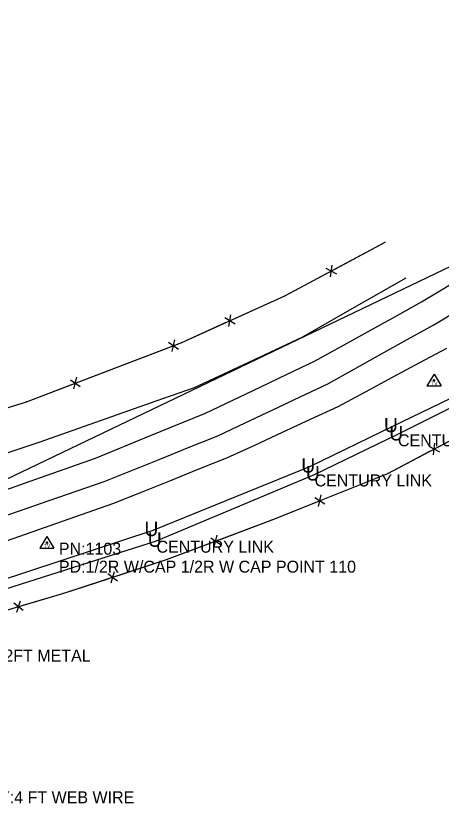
# Model space of a CAD drawing. Extents: x 1568433 to 1572450, y 731863 to 733450.
# Drawn here: x 1571582.8 to 1571760.5, y 732326.6 to 732655.4 of the extents above; entities that cross this region are included whole.
import ezdxf

# ---------------------------------------------------------------- set-up
doc = ezdxf.new("R2010")
doc.units = 0
for name, color, linetype in [('Default', 7, 'Continuous'), ('S_BASELINE', 7, 'Continuous'), ('S_DITCHLINE', 7, 'Continuous'), ('S_EDGE_PAVEMENT', 7, 'Continuous'), ('S_FENCE', 7, 'Continuous'), ('S_FENCE_ANNOT', 7, 'Continuous'), ('S_GATE_ANNOT', 7, 'Continuous'), ('S_MSC_PT_SYM', 7, 'Continuous'), ('S_PAVEMENT_CROWN', 7, 'Continuous'), ('S_SECONDARY_CTL', 7, 'Continuous'), ('S_SECONDARY_CTL_ANNOT', 7, 'Continuous'), ('S_UNDERGROUND_CABLE', 7, 'Continuous'), ('S_UNDERGROUND_CABLE_ANNOT', 7, 'Continuous')]:
    doc.layers.add(name, color=color, linetype=linetype)

msp = doc.modelspace()

# ---------------------------------------------------------------- linework, layer by layer
at = {"layer": 'S_BASELINE'}
msp.add_line((1571317.07, 732336.49), (1571982.53, 732655.39), dxfattribs=at)
at = {"layer": 'S_DITCHLINE'}
msp.add_lwpolyline([(1571461.29, 732434), (1571470.26, 732441.76), (1571482.63, 732445.32), (1571495, 732448.87), (1571507.37, 732452.42), (1571519.74, 732455.98), (1571543.04, 732462.3), (1571566.34, 732468.63), (1571579.68, 732473.06), (1571593.02, 732477.5), (1571609.14, 732483.19), (1571625.26, 732488.88), (1571641.39, 732494.57), (1571657.51, 732500.25), (1571680.11, 732510.78), (1571702.7, 732521.31), (1571724.29, 732533.67), (1571745.87, 732546.03)], dxfattribs=at)
at = {"layer": 'S_EDGE_PAVEMENT'}
for points in [[(1571570.26, 732454.54), (1571593.17, 732462.65), (1571616.09, 732470.76), (1571639.09, 732480.13), (1571662.1, 732489.5), (1571673.46, 732494.91), (1571684.82, 732500.32), (1571696.18, 732505.73), (1571707.54, 732511.14), (1571718.73, 732517.33), (1571729.92, 732523.52), (1571741.11, 732529.71), (1571752.3, 732535.9), (1571773.57, 732548.77)], [(1571576.57, 732435.33), (1571599.95, 732443.58), (1571623.34, 732451.84), (1571635.24, 732456.57), (1571647.13, 732461.3), (1571659.03, 732466.04), (1571670.93, 732470.77), (1571682.57, 732476.16), (1571694.21, 732481.55), (1571705.85, 732486.94), (1571717.49, 732492.32), (1571728.82, 732498.42), (1571740.15, 732504.51), (1571751.48, 732510.6), (1571762.8, 732516.69)]]:
    msp.add_lwpolyline(points, dxfattribs=at)
at = {"layer": 'S_FENCE'}
for p, q in [((1571695.19, 732538.5), (1571737.1, 732560.88)), ((1571712.35, 732549.98), (1571716.81, 732547.72)), ((1571712.35, 732549.98), (1571716.81, 732547.72)), ((1571714.28, 732546.37), (1571714.88, 732551.33)), ((1571714.28, 732546.37), (1571714.88, 732551.33)), ((1571652.21, 732519.03), (1571695.19, 732538.5)), ((1571670.07, 732529.37), (1571674.37, 732526.82)), ((1571670.07, 732529.37), (1571674.37, 732526.82)), ((1571671.76, 732525.63), (1571672.68, 732530.55)), ((1571671.76, 732525.63), (1571672.68, 732530.55)), ((1571648.05, 732515.24), (1571649.25, 732520.09)), ((1571648.05, 732515.24), (1571649.25, 732520.09)), ((1571587.21, 732494.2), (1571652.21, 732519.03)), ((1571646.58, 732519.07), (1571650.72, 732516.26)), ((1571646.58, 732519.07), (1571650.72, 732516.26)), ((1571605.62, 732503.43), (1571609.75, 732500.62)), ((1571605.62, 732503.43), (1571609.75, 732500.62)), ((1571607.08, 732499.6), (1571608.29, 732504.45)), ((1571607.08, 732499.6), (1571608.29, 732504.45)), ((1571480.28, 732461.34), (1571587.21, 732494.2)), ((1571738.13, 732464.28), (1571780.79, 732486.82)), ((1571757.23, 732472.06), (1571757.84, 732477.01)), ((1571757.23, 732472.06), (1571757.84, 732477.01)), ((1571755.31, 732475.68), (1571759.76, 732473.39)), ((1571755.31, 732475.68), (1571759.76, 732473.39)), ((1571689.42, 732444.79), (1571738.13, 732464.28)), ((1571707.72, 732454.32), (1571711.9, 732451.58)), ((1571707.72, 732454.32), (1571711.9, 732451.58)), ((1571709.25, 732450.52), (1571710.38, 732455.38)), ((1571709.25, 732450.52), (1571710.38, 732455.38)), ((1571645.74, 732428.39), (1571689.42, 732444.79)), ((1571664.21, 732437.51), (1571668.33, 732434.68)), ((1571664.21, 732437.51), (1571668.33, 732434.68)), ((1571665.65, 732433.68), (1571666.89, 732438.52)), ((1571665.65, 732433.68), (1571666.89, 732438.52)), ((1571602.42, 732414.16), (1571645.74, 732428.39)), ((1571621.29, 732422.52), (1571625.29, 732419.52)), ((1571621.29, 732422.52), (1571625.29, 732419.52)), ((1571622.57, 732418.62), (1571624.02, 732423.41)), ((1571622.57, 732418.62), (1571624.02, 732423.41)), ((1571562.86, 732402.61), (1571602.42, 732414.16)), ((1571583.17, 732406.4), (1571584.77, 732411.14)), ((1571583.17, 732406.4), (1571584.77, 732411.14)), ((1571582.02, 732410.34), (1571585.92, 732407.21)), ((1571582.02, 732410.34), (1571585.92, 732407.21))]:
    msp.add_line(p, q, dxfattribs=at)
for points in [[(1571716.34, 732549.79), (1571737.1, 732560.88)], [(1571716.34, 732549.79), (1571737.1, 732560.88)], [(1571695.19, 732538.5), (1571712.82, 732547.91)], [(1571695.19, 732538.5), (1571712.82, 732547.91)], [(1571674.04, 732528.92), (1571695.19, 732538.5)], [(1571674.04, 732528.92), (1571695.19, 732538.5)], [(1571652.21, 732519.03), (1571670.4, 732527.27)], [(1571652.21, 732519.03), (1571670.4, 732527.27)], [(1571609.55, 732502.73), (1571646.79, 732516.96)], [(1571609.55, 732502.73), (1571646.79, 732516.96)], [(1571649.99, 732518.18), (1571652.21, 732519.03)], [(1571649.99, 732518.18), (1571652.21, 732519.03)], [(1571587.21, 732494.2), (1571605.83, 732501.31)], [(1571587.21, 732494.2), (1571605.83, 732501.31)], [(1571567.4, 732488.12), (1571587.21, 732494.2)], [(1571567.4, 732488.12), (1571587.21, 732494.2)], [(1571759.3, 732475.47), (1571780.79, 732486.82)], [(1571759.3, 732475.47), (1571780.79, 732486.82)], [(1571738.13, 732464.28), (1571755.77, 732473.6)], [(1571738.13, 732464.28), (1571755.77, 732473.6)], [(1571711.67, 732453.69), (1571738.13, 732464.28)], [(1571711.67, 732453.69), (1571738.13, 732464.28)], [(1571689.42, 732444.79), (1571707.96, 732452.21)], [(1571689.42, 732444.79), (1571707.96, 732452.21)], [(1571668.14, 732436.8), (1571689.42, 732444.79)], [(1571668.14, 732436.8), (1571689.42, 732444.79)], [(1571645.74, 732428.39), (1571664.41, 732435.4)], [(1571645.74, 732428.39), (1571664.41, 732435.4)], [(1571625.19, 732421.64), (1571645.74, 732428.39)], [(1571625.19, 732421.64), (1571645.74, 732428.39)], [(1571602.42, 732414.16), (1571621.4, 732420.39)], [(1571602.42, 732414.16), (1571621.4, 732420.39)], [(1571585.89, 732409.33), (1571602.42, 732414.16)], [(1571585.89, 732409.33), (1571602.42, 732414.16)]]:
    msp.add_lwpolyline(points, dxfattribs=at)
at = {"layer": 'S_MSC_PT_SYM'}
for points in [[(1571737.1, 732560.88), (1571737.1, 732560.93), (1571737.1, 732560.88), (1571737.05, 732560.88), (1571737.1, 732560.88), (1571737.1, 732560.83), (1571737.1, 732560.88), (1571737.15, 732560.88)], [(1571695.19, 732538.5), (1571695.19, 732538.55), (1571695.19, 732538.5), (1571695.14, 732538.5), (1571695.19, 732538.5), (1571695.19, 732538.45), (1571695.19, 732538.5), (1571695.24, 732538.5)], [(1571652.21, 732519.03), (1571652.21, 732519.08), (1571652.21, 732519.03), (1571652.16, 732519.03), (1571652.21, 732519.03), (1571652.21, 732518.98), (1571652.21, 732519.03), (1571652.26, 732519.03)], [(1571587.21, 732494.2), (1571587.21, 732494.25), (1571587.21, 732494.2), (1571587.16, 732494.2), (1571587.21, 732494.2), (1571587.21, 732494.15), (1571587.21, 732494.2), (1571587.26, 732494.2)], [(1571738.13, 732464.28), (1571738.13, 732464.33), (1571738.13, 732464.28), (1571738.08, 732464.28), (1571738.13, 732464.28), (1571738.13, 732464.23), (1571738.13, 732464.28), (1571738.18, 732464.28)], [(1571689.42, 732444.79), (1571689.42, 732444.84), (1571689.42, 732444.79), (1571689.37, 732444.79), (1571689.42, 732444.79), (1571689.42, 732444.74), (1571689.42, 732444.79), (1571689.47, 732444.79)], [(1571645.74, 732428.39), (1571645.74, 732428.44), (1571645.74, 732428.39), (1571645.69, 732428.39), (1571645.74, 732428.39), (1571645.74, 732428.34), (1571645.74, 732428.39), (1571645.79, 732428.39)], [(1571602.42, 732414.16), (1571602.42, 732414.21), (1571602.42, 732414.16), (1571602.37, 732414.16), (1571602.42, 732414.16), (1571602.42, 732414.11), (1571602.42, 732414.16), (1571602.47, 732414.16)]]:
    msp.add_lwpolyline(points, dxfattribs=at)
at = {"layer": 'S_PAVEMENT_CROWN'}
msp.add_lwpolyline([(1571573.79, 732445.09), (1571596.75, 732453.01), (1571619.72, 732460.93), (1571631.57, 732465.7), (1571643.43, 732470.47), (1571655.28, 732475.23), (1571667.13, 732480), (1571678.62, 732485.43), (1571690.11, 732490.87), (1571701.59, 732496.3), (1571713.08, 732501.73), (1571724.14, 732507.9), (1571735.21, 732514.08), (1571746.27, 732520.25), (1571757.34, 732526.42), (1571768.19, 732532.96)], dxfattribs=at)
at = {"layer": 'S_SECONDARY_CTL'}
for p, q in [((1571757.52, 732505.78), (1571754.51, 732500.83)), ((1571757.52, 732505.78), (1571760.47, 732500.83)), ((1571754.51, 732500.83), (1571760.47, 732500.83)), ((1571595.79, 732438.01), (1571592.78, 732433.06)), ((1571595.79, 732438.01), (1571598.73, 732433.06)), ((1571592.78, 732433.06), (1571598.73, 732433.06))]:
    msp.add_line(p, q, dxfattribs=at)
for centre, radius in [((1571757.52, 732503.17), 0.311), ((1571757.52, 732503.17), 0.183), ((1571757.52, 732503.17), 0.103), ((1571595.79, 732435.4), 0.311), ((1571595.79, 732435.4), 0.183), ((1571595.79, 732435.4), 0.103)]:
    msp.add_circle(centre, radius, dxfattribs=at)
at = {"layer": 'S_UNDERGROUND_CABLE'}
for p, q in [((1571740.21, 732484.06), (1571774.59, 732500.7)), ((1571742.41, 732480.65), (1571775.74, 732497.5)), ((1571705.67, 732467.18), (1571740.21, 732484.06)), ((1571707.6, 732463.9), (1571742.41, 732480.65)), ((1571640.17, 732440.67), (1571705.67, 732467.18)), ((1571641.59, 732436.23), (1571707.6, 732463.9)), ((1571518.63, 732400.68), (1571640.17, 732440.67)), ((1571491.08, 732388.34), (1571641.59, 732436.23))]:
    msp.add_line(p, q, dxfattribs=at)

# ---------------------------------------------------------------- texts
at = {"layer": 'Default'}
for p in [(1571736.58, 732481.52), (1571738.78, 732478.1), (1571702.04, 732464.64), (1571703.97, 732461.36), (1571636.54, 732438.13), (1571637.96, 732433.69)]:
    msp.add_text('U', height=6, dxfattribs=at).set_placement(p)
at = {"layer": 'S_FENCE_ANNOT'}
msp.add_text('TY:4 FT WEB WIRE', height=5, dxfattribs=at).set_placement((1571571.75, 732326.64))
at = {"layer": 'S_GATE_ANNOT'}
msp.add_text('TY:12FT METAL', height=5, dxfattribs=at).set_placement((1571563.92, 732385.77))
at = {"layer": 'S_SECONDARY_CTL'}
msp.add_text('TV', height=1.5, rotation=360, dxfattribs=at).set_placement((1571756.32, 732501.16))
msp.add_text('TV', height=1.5, dxfattribs=at).set_placement((1571594.58, 732433.39))
at = {"layer": 'S_SECONDARY_CTL_ANNOT'}
for s, p in [('PN:1103', (1571600.79, 732430.4)), ('PD:1/2R W/CAP 1/2R W CAP POINT 110', (1571600.79, 732422.9))]:
    msp.add_text(s, height=5, dxfattribs=at).set_placement(p)
at = {"layer": 'S_UNDERGROUND_CABLE_ANNOT'}
for p in [(1571742.41, 732475.65), (1571707.6, 732458.9), (1571641.59, 732431.23)]:
    msp.add_text('CENTURY LINK', height=5, dxfattribs=at).set_placement(p)

doc.saveas('drawing.dxf')
